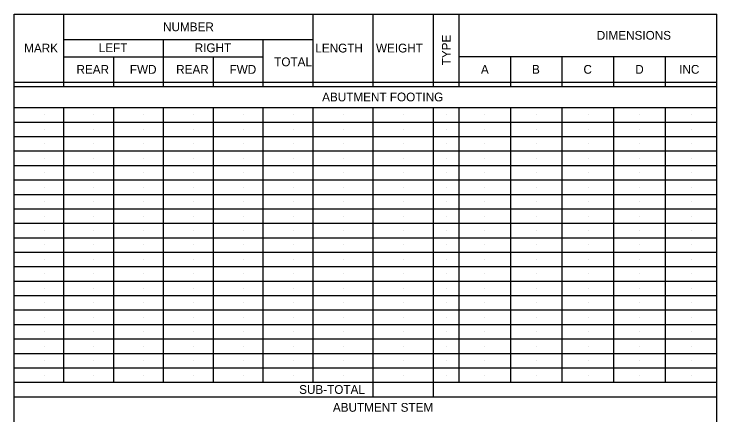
# Model space of a CAD drawing. Extents: x -16.6 to 33.3, y -8.6 to 39.2.
# Drawn here: x -16.64 to -3, y 12.95 to 20.71 of the extents above; entities that cross this region are included whole.
import ezdxf

# ---------------------------------------------------------------- set-up
doc = ezdxf.new("R2010")
doc.units = 0
doc.layers.add('BR_X_Beam_Centerline', color=7, linetype='Continuous')

msp = doc.modelspace()

# ---------------------------------------------------------------- linework, layer by layer
at = {"layer": 'BR_X_Beam_Centerline'}
for p, q in [((-16.637, 20.715), (-3.003, 20.715)), ((-16.637, 7.291), (-16.637, 20.715)), ((-15.67, 19.315), (-15.67, 20.715)), ((-10.837, 19.314), (-10.837, 20.715)), ((-9.67, 19.315), (-9.67, 20.715)), ((-8.503, 19.315), (-8.503, 20.715)), ((-8.003, 19.315), (-8.003, 20.715)), ((-3.003, 7.291), (-3.003, 20.715)), ((-15.67, 20.221), (-10.837, 20.221)), ((-13.737, 19.315), (-13.737, 20.221)), ((-11.803, 19.315), (-11.803, 20.221)), ((-15.67, 19.889), (-11.803, 19.888)), ((-14.703, 19.315), (-14.703, 19.889)), ((-12.77, 19.315), (-12.77, 19.888)), ((-8.003, 19.891), (-3.003, 19.891)), ((-7.003, 19.314), (-7.003, 19.891)), ((-6.003, 19.314), (-6.003, 19.891)), ((-5.003, 19.314), (-5.003, 19.891)), ((-4.003, 19.315), (-4.003, 19.891)), ((-4.003, 19.314), (-4.003, 19.891)), ((-15.087, 19.643), (-15.087, 19.643)), ((-14.12, 19.643), (-14.12, 19.643)), ((-13.153, 19.643), (-13.153, 19.643)), ((-12.187, 19.643), (-12.187, 19.643)), ((-16.637, 19.397), (-3.003, 19.397)), ((-16.637, 19.315), (-3.003, 19.315)), ((-9.42, 19.109), (-9.42, 19.109)), ((-16.637, 18.903), (-3.003, 18.903)), ((-15.67, 13.583), (-15.67, 18.903)), ((-14.703, 13.583), (-14.703, 18.903)), ((-13.737, 13.583), (-13.737, 18.903)), ((-12.77, 13.583), (-12.77, 18.903)), ((-11.803, 13.583), (-11.803, 18.903)), ((-10.837, 13.583), (-10.837, 18.903)), ((-9.67, 13.303), (-9.67, 18.903)), ((-8.503, 13.303), (-8.503, 18.903)), ((-8.003, 13.583), (-8.003, 18.903)), ((-7.003, 13.583), (-7.003, 18.903)), ((-6.003, 13.583), (-6.003, 18.903)), ((-5.003, 13.583), (-5.003, 18.903)), ((-4.003, 13.583), (-4.003, 18.903)), ((-4.003, 13.583), (-4.003, 18.903)), ((-16.053, 18.763), (-16.053, 18.763)), ((-15.087, 18.763), (-15.087, 18.763)), ((-14.12, 18.763), (-14.12, 18.763)), ((-13.153, 18.763), (-13.153, 18.763)), ((-12.187, 18.763), (-12.187, 18.763)), ((-11.22, 18.763), (-11.22, 18.763)), ((-10.253, 18.763), (-10.253, 18.763)), ((-9.087, 18.763), (-9.087, 18.763)), ((-8.253, 18.763), (-8.253, 18.763)), ((-7.503, 18.763), (-7.503, 18.763)), ((-6.503, 18.763), (-6.503, 18.763)), ((-5.503, 18.763), (-5.503, 18.763)), ((-4.503, 18.763), (-4.503, 18.763)), ((-3.503, 18.763), (-3.503, 18.763)), ((-16.637, 18.623), (-3.003, 18.623)), ((-16.053, 18.483), (-16.053, 18.483)), ((-15.087, 18.483), (-15.087, 18.483)), ((-14.12, 18.483), (-14.12, 18.483)), ((-13.153, 18.483), (-13.153, 18.483)), ((-12.187, 18.483), (-12.187, 18.483)), ((-11.22, 18.483), (-11.22, 18.483)), ((-10.253, 18.483), (-10.253, 18.483)), ((-9.087, 18.483), (-9.087, 18.483)), ((-8.253, 18.483), (-8.253, 18.483)), ((-7.503, 18.483), (-7.503, 18.483)), ((-6.503, 18.483), (-6.503, 18.483)), ((-5.503, 18.483), (-5.503, 18.483)), ((-4.503, 18.483), (-4.503, 18.483)), ((-3.503, 18.483), (-3.503, 18.483)), ((-16.637, 18.343), (-3.003, 18.343)), ((-16.053, 18.203), (-16.053, 18.203)), ((-15.087, 18.203), (-15.087, 18.203)), ((-14.12, 18.203), (-14.12, 18.203)), ((-13.153, 18.203), (-13.153, 18.203)), ((-12.187, 18.203), (-12.187, 18.203)), ((-11.22, 18.203), (-11.22, 18.203)), ((-10.253, 18.203), (-10.253, 18.203)), ((-9.087, 18.203), (-9.087, 18.203)), ((-8.253, 18.203), (-8.253, 18.203)), ((-7.503, 18.203), (-7.503, 18.203)), ((-6.503, 18.203), (-6.503, 18.203)), ((-5.503, 18.203), (-5.503, 18.203)), ((-4.503, 18.203), (-4.503, 18.203)), ((-3.503, 18.203), (-3.503, 18.203)), ((-16.637, 18.063), (-3.003, 18.063)), ((-16.053, 17.923), (-16.053, 17.923)), ((-15.087, 17.923), (-15.087, 17.923)), ((-14.12, 17.923), (-14.12, 17.923)), ((-13.153, 17.923), (-13.153, 17.923)), ((-12.187, 17.923), (-12.187, 17.923)), ((-11.22, 17.923), (-11.22, 17.923)), ((-10.253, 17.923), (-10.253, 17.923)), ((-9.087, 17.923), (-9.087, 17.923)), ((-8.253, 17.923), (-8.253, 17.923)), ((-7.503, 17.923), (-7.503, 17.923)), ((-6.503, 17.923), (-6.503, 17.923)), ((-5.503, 17.923), (-5.503, 17.923)), ((-4.503, 17.923), (-4.503, 17.923)), ((-3.503, 17.923), (-3.503, 17.923)), ((-16.637, 17.783), (-3.003, 17.783)), ((-16.053, 17.643), (-16.053, 17.643)), ((-15.087, 17.643), (-15.087, 17.643)), ((-14.12, 17.643), (-14.12, 17.643)), ((-13.153, 17.643), (-13.153, 17.643)), ((-12.187, 17.643), (-12.187, 17.643)), ((-11.22, 17.643), (-11.22, 17.643)), ((-10.253, 17.643), (-10.253, 17.643)), ((-9.087, 17.643), (-9.087, 17.643)), ((-8.253, 17.643), (-8.253, 17.643)), ((-7.503, 17.643), (-7.503, 17.643)), ((-6.503, 17.643), (-6.503, 17.643)), ((-5.503, 17.643), (-5.503, 17.643)), ((-4.503, 17.643), (-4.503, 17.643)), ((-3.503, 17.643), (-3.503, 17.643)), ((-16.637, 17.503), (-3.003, 17.503)), ((-16.053, 17.363), (-16.053, 17.363)), ((-15.087, 17.363), (-15.087, 17.363)), ((-14.12, 17.363), (-14.12, 17.363)), ((-13.153, 17.363), (-13.153, 17.363)), ((-12.187, 17.363), (-12.187, 17.363)), ((-11.22, 17.363), (-11.22, 17.363)), ((-10.253, 17.363), (-10.253, 17.363)), ((-9.087, 17.363), (-9.087, 17.363)), ((-8.253, 17.363), (-8.253, 17.363)), ((-7.503, 17.363), (-7.503, 17.363)), ((-6.503, 17.363), (-6.503, 17.363)), ((-5.503, 17.363), (-5.503, 17.363)), ((-4.503, 17.363), (-4.503, 17.363)), ((-3.503, 17.363), (-3.503, 17.363)), ((-16.637, 17.223), (-3.003, 17.223)), ((-16.053, 17.083), (-16.053, 17.083)), ((-15.087, 17.083), (-15.087, 17.083)), ((-14.12, 17.083), (-14.12, 17.083)), ((-13.153, 17.083), (-13.153, 17.083)), ((-12.187, 17.083), (-12.187, 17.083)), ((-11.22, 17.083), (-11.22, 17.083)), ((-10.253, 17.083), (-10.253, 17.083)), ((-9.087, 17.083), (-9.087, 17.083)), ((-8.253, 17.083), (-8.253, 17.083)), ((-7.503, 17.083), (-7.503, 17.083)), ((-6.503, 17.083), (-6.503, 17.083)), ((-5.503, 17.083), (-5.503, 17.083)), ((-4.503, 17.083), (-4.503, 17.083)), ((-3.503, 17.083), (-3.503, 17.083)), ((-16.637, 16.943), (-3.003, 16.943)), ((-16.053, 16.803), (-16.053, 16.803)), ((-15.087, 16.803), (-15.087, 16.803)), ((-14.12, 16.803), (-14.12, 16.803)), ((-13.153, 16.803), (-13.153, 16.803)), ((-12.187, 16.803), (-12.187, 16.803)), ((-11.22, 16.803), (-11.22, 16.803)), ((-10.253, 16.803), (-10.253, 16.803)), ((-9.087, 16.803), (-9.087, 16.803)), ((-8.253, 16.803), (-8.253, 16.803)), ((-7.503, 16.803), (-7.503, 16.803)), ((-6.503, 16.803), (-6.503, 16.803)), ((-5.503, 16.803), (-5.503, 16.803)), ((-4.503, 16.803), (-4.503, 16.803)), ((-3.503, 16.803), (-3.503, 16.803)), ((-16.637, 16.663), (-3.003, 16.663)), ((-16.053, 16.523), (-16.053, 16.523)), ((-15.087, 16.523), (-15.087, 16.523)), ((-14.12, 16.523), (-14.12, 16.523)), ((-13.153, 16.523), (-13.153, 16.523)), ((-12.187, 16.523), (-12.187, 16.523)), ((-11.22, 16.523), (-11.22, 16.523)), ((-10.253, 16.523), (-10.253, 16.523)), ((-9.087, 16.523), (-9.087, 16.523)), ((-8.253, 16.523), (-8.253, 16.523)), ((-7.503, 16.523), (-7.503, 16.523)), ((-6.503, 16.523), (-6.503, 16.523)), ((-5.503, 16.523), (-5.503, 16.523)), ((-4.503, 16.523), (-4.503, 16.523)), ((-3.503, 16.523), (-3.503, 16.523)), ((-16.637, 16.383), (-3.003, 16.383)), ((-16.053, 16.243), (-16.053, 16.243)), ((-15.087, 16.243), (-15.087, 16.243)), ((-14.12, 16.243), (-14.12, 16.243)), ((-13.153, 16.243), (-13.153, 16.243)), ((-12.187, 16.243), (-12.187, 16.243)), ((-11.22, 16.243), (-11.22, 16.243)), ((-10.253, 16.243), (-10.253, 16.243)), ((-9.087, 16.243), (-9.087, 16.243)), ((-8.253, 16.243), (-8.253, 16.243)), ((-7.503, 16.243), (-7.503, 16.243)), ((-6.503, 16.243), (-6.503, 16.243)), ((-5.503, 16.243), (-5.503, 16.243)), ((-4.503, 16.243), (-4.503, 16.243)), ((-3.503, 16.243), (-3.503, 16.243)), ((-16.637, 16.103), (-3.003, 16.103)), ((-16.053, 15.963), (-16.053, 15.963)), ((-15.087, 15.963), (-15.087, 15.963)), ((-14.12, 15.963), (-14.12, 15.963)), ((-13.153, 15.963), (-13.153, 15.963)), ((-12.187, 15.963), (-12.187, 15.963)), ((-11.22, 15.963), (-11.22, 15.963)), ((-10.253, 15.963), (-10.253, 15.963)), ((-9.087, 15.963), (-9.087, 15.963)), ((-8.253, 15.963), (-8.253, 15.963)), ((-7.503, 15.963), (-7.503, 15.963)), ((-6.503, 15.963), (-6.503, 15.963)), ((-5.503, 15.963), (-5.503, 15.963)), ((-4.503, 15.963), (-4.503, 15.963)), ((-3.503, 15.963), (-3.503, 15.963)), ((-16.637, 15.823), (-3.003, 15.823)), ((-16.053, 15.683), (-16.053, 15.683)), ((-15.087, 15.683), (-15.087, 15.683)), ((-14.12, 15.683), (-14.12, 15.683)), ((-13.153, 15.683), (-13.153, 15.683)), ((-12.187, 15.683), (-12.187, 15.683)), ((-11.22, 15.683), (-11.22, 15.683)), ((-10.253, 15.683), (-10.253, 15.683)), ((-9.087, 15.683), (-9.087, 15.683)), ((-8.253, 15.683), (-8.253, 15.683)), ((-7.503, 15.683), (-7.503, 15.683)), ((-6.503, 15.683), (-6.503, 15.683)), ((-5.503, 15.683), (-5.503, 15.683)), ((-4.503, 15.683), (-4.503, 15.683)), ((-3.503, 15.683), (-3.503, 15.683)), ((-16.637, 15.543), (-3.003, 15.543)), ((-16.053, 15.403), (-16.053, 15.403)), ((-15.087, 15.403), (-15.087, 15.403)), ((-14.12, 15.403), (-14.12, 15.403)), ((-13.153, 15.403), (-13.153, 15.403)), ((-12.187, 15.403), (-12.187, 15.403)), ((-11.22, 15.403), (-11.22, 15.403)), ((-10.253, 15.403), (-10.253, 15.403)), ((-9.087, 15.403), (-9.087, 15.403)), ((-8.253, 15.403), (-8.253, 15.403)), ((-7.503, 15.403), (-7.503, 15.403)), ((-6.503, 15.403), (-6.503, 15.403)), ((-5.503, 15.403), (-5.503, 15.403)), ((-4.503, 15.403), (-4.503, 15.403)), ((-3.503, 15.403), (-3.503, 15.403)), ((-16.637, 15.263), (-3.003, 15.263)), ((-16.053, 15.123), (-16.053, 15.123)), ((-15.087, 15.123), (-15.087, 15.123)), ((-14.12, 15.123), (-14.12, 15.123)), ((-13.153, 15.123), (-13.153, 15.123)), ((-12.187, 15.123), (-12.187, 15.123)), ((-11.22, 15.123), (-11.22, 15.123)), ((-10.253, 15.123), (-10.253, 15.123)), ((-9.087, 15.123), (-9.087, 15.123)), ((-8.253, 15.123), (-8.253, 15.123)), ((-7.503, 15.123), (-7.503, 15.123)), ((-6.503, 15.123), (-6.503, 15.123)), ((-5.503, 15.123), (-5.503, 15.123)), ((-4.503, 15.123), (-4.503, 15.123)), ((-3.503, 15.123), (-3.503, 15.123)), ((-16.637, 14.983), (-3.003, 14.983)), ((-16.053, 14.843), (-16.053, 14.843)), ((-15.087, 14.843), (-15.087, 14.843)), ((-14.12, 14.843), (-14.12, 14.843)), ((-13.153, 14.843), (-13.153, 14.843)), ((-12.187, 14.843), (-12.187, 14.843)), ((-11.22, 14.843), (-11.22, 14.843)), ((-10.253, 14.843), (-10.253, 14.843)), ((-9.087, 14.843), (-9.087, 14.843)), ((-8.253, 14.843), (-8.253, 14.843)), ((-7.503, 14.843), (-7.503, 14.843)), ((-6.503, 14.843), (-6.503, 14.843)), ((-5.503, 14.843), (-5.503, 14.843)), ((-4.503, 14.843), (-4.503, 14.843)), ((-3.503, 14.843), (-3.503, 14.843)), ((-16.637, 14.703), (-3.003, 14.703)), ((-16.053, 14.563), (-16.053, 14.563)), ((-15.087, 14.563), (-15.087, 14.563)), ((-14.12, 14.563), (-14.12, 14.563)), ((-13.153, 14.563), (-13.153, 14.563)), ((-12.187, 14.563), (-12.187, 14.563)), ((-11.22, 14.563), (-11.22, 14.563)), ((-10.253, 14.563), (-10.253, 14.563)), ((-9.087, 14.563), (-9.087, 14.563)), ((-8.253, 14.563), (-8.253, 14.563)), ((-7.503, 14.563), (-7.503, 14.563)), ((-6.503, 14.563), (-6.503, 14.563)), ((-5.503, 14.563), (-5.503, 14.563)), ((-4.503, 14.563), (-4.503, 14.563)), ((-3.503, 14.563), (-3.503, 14.563)), ((-16.637, 14.423), (-3.003, 14.423)), ((-16.053, 14.283), (-16.053, 14.283)), ((-15.087, 14.283), (-15.087, 14.283)), ((-14.12, 14.283), (-14.12, 14.283)), ((-13.153, 14.283), (-13.153, 14.283)), ((-12.187, 14.283), (-12.187, 14.283)), ((-11.22, 14.283), (-11.22, 14.283)), ((-10.253, 14.283), (-10.253, 14.283)), ((-9.087, 14.283), (-9.087, 14.283)), ((-8.253, 14.283), (-8.253, 14.283)), ((-7.503, 14.283), (-7.503, 14.283)), ((-6.503, 14.283), (-6.503, 14.283)), ((-5.503, 14.283), (-5.503, 14.283)), ((-4.503, 14.283), (-4.503, 14.283)), ((-3.503, 14.283), (-3.503, 14.283)), ((-16.637, 14.143), (-3.003, 14.143)), ((-16.053, 14.003), (-16.053, 14.003)), ((-15.087, 14.003), (-15.087, 14.003)), ((-14.12, 14.003), (-14.12, 14.003)), ((-13.153, 14.003), (-13.153, 14.003)), ((-12.187, 14.003), (-12.187, 14.003)), ((-11.22, 14.003), (-11.22, 14.003)), ((-10.253, 14.003), (-10.253, 14.003)), ((-9.087, 14.003), (-9.087, 14.003)), ((-8.253, 14.003), (-8.253, 14.003)), ((-7.503, 14.003), (-7.503, 14.003)), ((-6.503, 14.003), (-6.503, 14.003)), ((-5.503, 14.003), (-5.503, 14.003)), ((-4.503, 14.003), (-4.503, 14.003)), ((-3.503, 14.003), (-3.503, 14.003)), ((-16.637, 13.863), (-3.003, 13.863)), ((-16.053, 13.723), (-16.053, 13.723)), ((-15.087, 13.723), (-15.087, 13.723)), ((-14.12, 13.723), (-14.12, 13.723)), ((-13.153, 13.723), (-13.153, 13.723)), ((-12.187, 13.723), (-12.187, 13.723)), ((-11.22, 13.723), (-11.22, 13.723)), ((-10.253, 13.723), (-10.253, 13.723)), ((-9.087, 13.723), (-9.087, 13.723)), ((-8.253, 13.723), (-8.253, 13.723)), ((-7.503, 13.723), (-7.503, 13.723)), ((-6.503, 13.723), (-6.503, 13.723)), ((-5.503, 13.723), (-5.503, 13.723)), ((-4.503, 13.723), (-4.503, 13.723)), ((-3.503, 13.723), (-3.503, 13.723)), ((-16.637, 13.583), (-3.003, 13.583)), ((-16.637, 13.303), (-3.003, 13.303)), ((-9.42, 13.097), (-9.42, 13.097))]:
    msp.add_line(p, q, dxfattribs=at)

# ---------------------------------------------------------------- texts
for s, p in [('NUMBER', (-13.747, 20.383)), ('DIMENSIONS', (-5.334, 20.218)), ('MARK', (-16.441, 19.971)), ('LEFT', (-14.994, 19.977)), ('RIGHT', (-13.133, 19.977)), ('LENGTH', (-10.793, 19.971)), ('WEIGHT', (-9.617, 19.971)), ('TOTAL', (-11.591, 19.704)), ('REAR', (-15.426, 19.558)), ('FWD', (-14.391, 19.558)), ('REAR', (-13.492, 19.558)), ('FWD', (-12.457, 19.558)), ('A', (-7.581, 19.559)), ('B', (-6.59, 19.559)), ('C', (-5.592, 19.559)), ('D', (-4.588, 19.559)), ('INC', (-3.735, 19.559)), ('ABUTMENT FOOTING', (-10.661, 19.024)), ('SUB-TOTAL', (-11.107, 13.358)), ('ABUTMENT STEM', (-10.452, 13.012))]:
    msp.add_text(s, height=0.17, dxfattribs=at).set_placement(p)
msp.add_text('TYPE', height=0.17, rotation=90, dxfattribs=at).set_placement((-8.168, 19.722))

doc.saveas('drawing.dxf')
